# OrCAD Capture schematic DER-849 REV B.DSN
size B
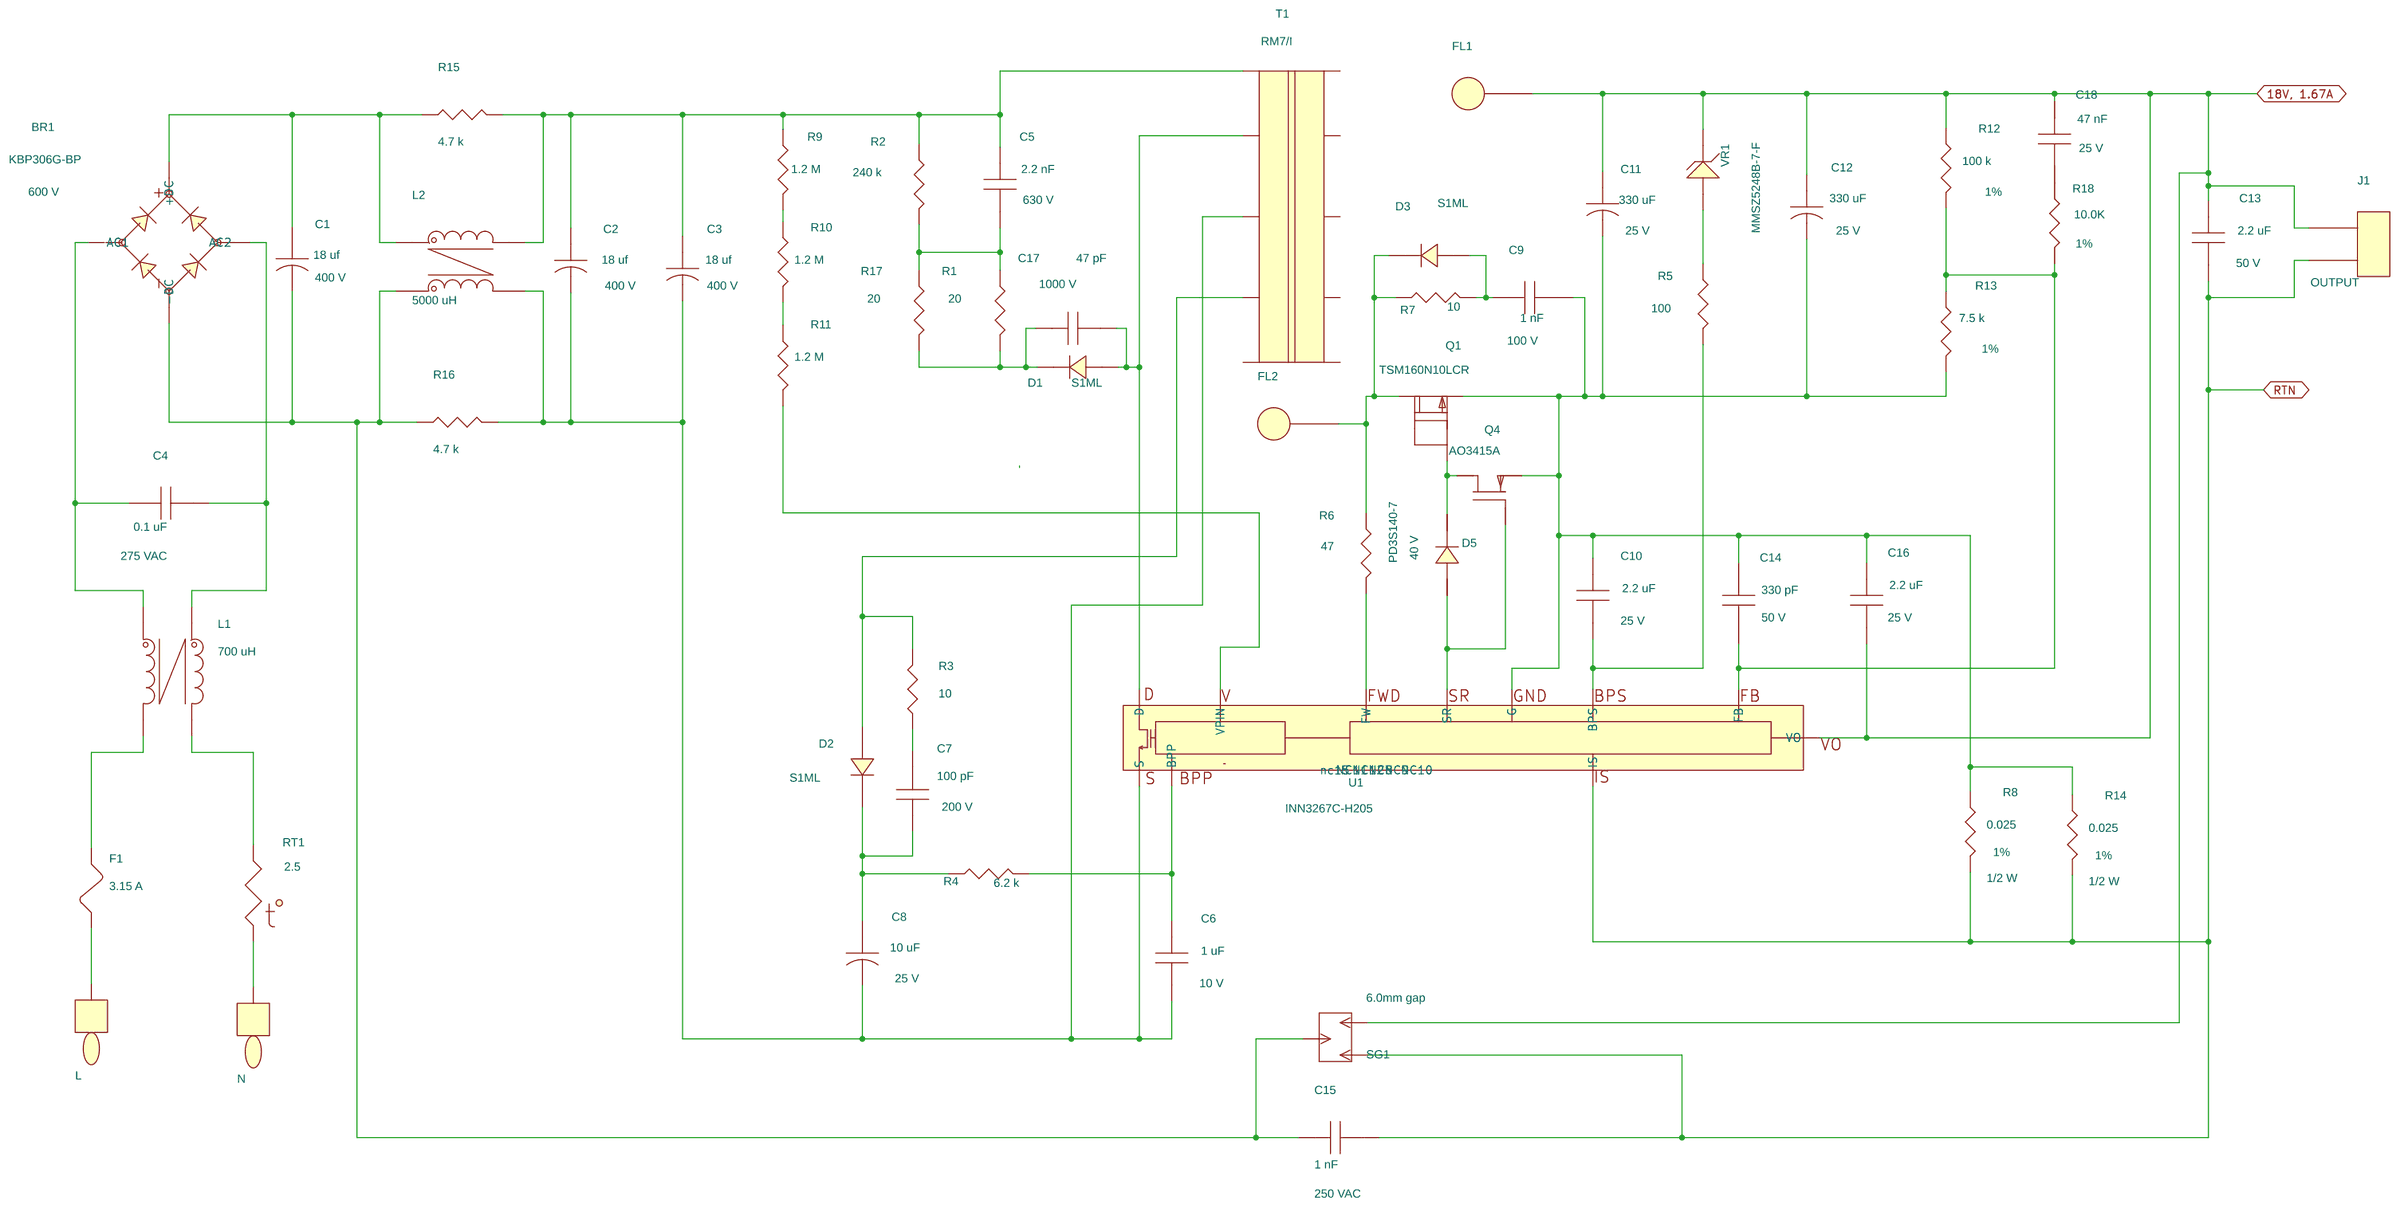
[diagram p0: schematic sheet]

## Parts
BR1  KBP306G-BP  [pidaxbridgeKBP306G]
C1  18 uf  [pipolcapcyld400ls200040]
C2  18 uf  [pipolcapcyld400ls200040]
C3  18 uf  [pipolcapcyld400ls200040]
C4  0.1 uF  [pinpxcaprad5x13x11p1mm040]
C5  2.2 nF  [pismc1206]
C6  1 uF  [pismc0805]
C7  100 pF  [pismc0603]
C8  10 uF  [pipolcapclyd200ls80030]
C9  1 nF  [pismc0603]
C10  2.2 uF  [pismc0805]
C11  330 uF  [pipolcapcyld315ls138d030]
C12  330 uF  [pipolcapcyld315ls138d030]
C13  2.2 uF  [pismc0805]
C14  330 pF  [pismc0603]
C15  1 nF  [pinpycaprad540x290ls400040]
C16  2.2 uF  [pismc0805]
C17  47 pF  [pismc0805]
C18  47 nF  [pismc0603]
D1  S1ML  [pi_sm_sod-123_12]
D2  S1ML  [pi_sm_sod-123_12]
D3  S1ML  [pi_sm_sod-123_12]
D5  PD3S140-7  [pismd_powerdi323]
F1  3.15 A  [pi_rst_microfuse]
FL1  Hole_50mils  [pi_hole_50mil]
FL2  Hole_50mils  [pi_hole_50mil]
J1  OUTPUT  [pi_molex_2_100_header]
L1  700 uH  [pi_4p_10xd4mmd40]
L2  5000 uH  [pi_4p_10xd4mmd40]
Q1  TSM160N10LCR  [pismpqfn5x6b]
Q4  AO3415A  [pismsot23123_1]
R1  20  [pismr1206]
R2  240 k  [pismr1206]
R3  10  [pismr0805]
R4  6.2 k  [pismr0603]
R5  100  [pismr0603]
R6  47  [pismr0603]
R7  10  [pismr0805]
R8  0.025  [pismr1206]
R9  1.2 M  [pismr0805]
R10  1.2 M  [pismr0805]
R11  1.2 M  [pismr0805]
R12  100 k  [pismr0603]
R13  7.5 k  [pismr0603]
R14  0.025  [pismr1206]
R15  4.7 k  [pismr0805]
R16  4.7 k  [pismr0805]
R17  20  [pismr1206]
R18  10.0K  [pismr0603]
RT1  2.5  [pi_rad150x300ls200d030]
SG1  6.0mm gap  [PI_SPARK_GAP_6p5MM_3p]
T1  RM7/I  [pi_bobbin_rm7_8p_clp]
TP1  N  [pitpkeystone100x100]
TP2  L  [pitpkeystone100x100]
U1  INN3267C-H205  [pi_ic_insop_24d]
VR1  MMSZ5248B-7-F  [pi_sm_sod-123_12]

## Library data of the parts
BR1 = DISCRETE_BRIDGE_+~~-: Disp_Voltage: 600 V; Part Number: 15-01300-00
C1-C3 = CAP_POL: ALT_SYMBOLS: pipolcapclyd395x630ls200030h; Disp_Voltage: 400 V; FPLIST: pipolcapcyld400ls200040,pipolcapclyd395x630ls200030h; Part Number: 20-09063-00; Voltage: 400 V
C4 = CAP_NP: ALT_SYMBOLS: pinpxcaprad5x13x11p1mm040h; Disp_Voltage: 275 VAC; FPLIST: pinpxcaprad5x13x11p1mm040,pinpxcaprad5x13x11p1mm040h; Part Number: 20-09109-00; Voltage: 275 VAC
C5 = CAP_NP: Disp_Voltage: 630 V; Part Number: 20-08609-00; Voltage: 630 V
C6 = CAP_NP: Disp_Voltage: 10 V; Part Number: 20-08953-00; Voltage: 10 V
C7 = CAP_NP: Disp_Voltage: 200 V; Part Number: 20-01178-00; Voltage: 200 V
C8 = CAP_POL: ALT_SYMBOLS: pipolcapclyd200ls80030h; Disp_Voltage: 25 V; FPLIST: pipolcapclyd200ls80030,pipolcapclyd200ls80030h; Part Number: 20-01182-00; Voltage: 25 V
C9 = CAP_NP: Disp_Voltage: 100 V; Part Number: 20-00712-00; Voltage: 100 V
C10 C16 = CAP_NP: Disp_Voltage: 25 V; Part Number: 20-08603-00; Voltage: 25 V
C11 C12 = CAP_POL: ALT_SYMBOLS: pipolcapcyld315ls138d030h; Disp_Voltage: 25 V; FPLIST: pipolcapcyld315ls138d030,pipolcapcyld315ls138d030h; Part Number: 20-09107-00; Voltage: 25 V
C13 = CAP_NP: Disp_Voltage: 50 V; Part Number: 20-09011-00; Voltage: 50 V
C14 = CAP_NP: ALT_SYMBOLS: pismc0603_1; Disp_Voltage: 50 V; FPLIST: pismc0603,pismc0603_1; Part Number: 20-09235-00; Voltage: 50 V
C15 = CAP_NP: ALT_SYMBOLS: pinpycaprad540x290ls400040h,pinpycaprad500x220ls400040; Disp_Voltage: 250 VAC; FPLIST: pinpycaprad540x290ls400040,pinpycaprad540x290ls400040h,pinpycaprad500x220ls400040; Part Number: 20-00375-00; Voltage: 250 VAC
C17 = CAP_NP: Disp_Voltage: 1000 V; Part Number: 20-01040-00; Voltage: 1000 V
C18 = CAP_NP: Disp_Voltage: 25 V; Part Number: 20-08756-00; Voltage: 25 V
D1-D3 = DIODE: Part Number: 15-01027-00
D5 = DIODE: Disp_Voltage: 40 V; Part Number: 15-01025-00
F1 = FUSE: ALT_SYMBOLS: pirstmicrofusehoz; FPLIST: pi_rst_microfuse,pirstmicrofusehoz; Part Number: 40-00020-00
FL1 FL2 = FlyingLead: Part Number: 35-00283-00
J1 = CON2: Part Number: 35-00015-00
L1 = TORRID_4P_21_34: Part Number: 32-00395-00
L2 = TORRID_4P_21_34: Part Number: 32-00396-00
Q1 = FET_N_SGD_123_4_5678: Part Number: 50-00280-00
Q4 = FET_P_GSD: Part Number: 50-00292-00
R1 R17 = R: Part Number: 05-01311-00
R2 = R: Part Number: 05-01409-00
R3 R7 = R: Part Number: 05-01471-00
R4 = R: Part Number: 05-01707-00
R5 = R: Part Number: 05-01664-00
R6 = R: ALT_SYMBOLS: pismr0603_1; FPLIST: pismr0603,pismr0603_1; Part Number: 05-01656-00
R8 R14 = R: Disp_Power: 1/2 W; Disp_Tol: 1%; Part Number: 05-06301-00
R9-R11 = R: Part Number: 05-01593-00
R12 = R: Disp_Tol: 1%; Part Number: 05-01174-00
R13 = R: Disp_Tol: 1%; Part Number: 05-01162-00
R15 R16 = R: Part Number: 05-01535-00
R18 = R: Disp_Tol: 1%; Part Number: 05-06492-00
RT1 = THERMISTOR: ALT_SYMBOLS: pirad400x300ls200040_h; FPLIST: pi_rad150x300ls200d030,pirad400x300ls200040_h; Part Number: 90-00040-00
SG1 = SPARK_GAP_3p: Part Number: 66-00356-00
T1 = BRM7_8P_CLP_2: Part Number: 25-01014-00
TP1 = TESTPOINT: Part Number: 35-00079-00
TP2 = TESTPOINT: Part Number: 35-00081-00
U1 = Inno3CP: Part Number: 10-01042-00
VR1 = DIODE_ZENER: Part Number: 15-01105-00

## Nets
18V, 1.67A: C11.1 C12.1 C13.1 C16.2 C18.1 FL1.1 J1.1 R12.1 SG1.3 U1.6(VO) VR1.1
NC8: U1.8(NC8)
NC9: U1.9(NC9)
NC10: U1.10(NC10)
NC11: U1.11(NC11)
NC12: U1.12(NC12)
NC15: U1.15(nc15)
RTN: C13.2 C15.2 J1.2 R8.2 R14.2 SG1.2 U1.1(IS)
N12273366: F1.2 L1.1
N12273454: BR1.1(+DC) C1.1 L2.3 R15.1
N12273677: BR1.4(-DC) C1.2 C15.1 L2.2 R16.1 SG1.1
N12273859: C2.1 C3.1 C5.1 L2.4 R2.1 R9.1 R15.2 T1.4
N12273903: C2.2 C3.2 C6.2 C8.2 L2.1 R16.2 T1.3 U1.16(S)
N12275039: C5.2 R1.1 R2.2 R17.1
N12275267: C6.1 R4.2 U1.14(BPP)
N12275350: D2.2 R3.2 T1.2
N12275682: C7.2 R3.1
N12275686: C7.1 C8.1 D2.1 R4.1
N12279930: R6.2 U1.7(FW)
N12279938: D3.1 FL2.1 Q1.5(D) R6.1 R7.1
N12280045: C9.2 C10.1 C11.2 C12.2 C14.1 C16.1 Q1.1(S) Q4.3(D) R8.1 R13.2 R14.1 U1.2(G)
N12283028: R11.2 U1.13(VPIN)
N12284778: C14.2 R12.2 R13.1 R18.2 U1.3(FB)
N12285860: L1.4 RT1.1
N12290600: C9.1 D3.2 R7.2
N12292662: D5.1 Q1.4(G) Q4.2(S)
N12292685: D5.2 Q4.1(G) U1.5(SR)
N12293491: C10.2 R5.2 U1.4(BPS)
N12296994: R5.1 VR1.2
N12297940: BR1.3(AC2) C4.2 L1.3
N12297952: BR1.2(AC1) C4.1 L1.2
N12298342: C17.1 D1.1 R1.2 R17.2
N12298360: C17.2 D1.2 T1.5 U1.24(D)
N12331858: R9.2 R10.1
N12331878: R10.2 R11.1
N12332729: F1.1 TP2.1
N12332733: RT1.2 TP1.1
N12333789: C18.2 R18.1

Not connected (* = marked no-connect by the designer): Q1 2(S2) 3(S3) 6(D6) 7(D7) 8(D8); T1 1 6 7 8 CLP1 CLP2
